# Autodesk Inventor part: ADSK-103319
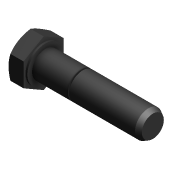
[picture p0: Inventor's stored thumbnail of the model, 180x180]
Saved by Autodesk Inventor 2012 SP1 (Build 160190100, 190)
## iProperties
Created: 2000-09
Part Number: ADSK-103319
Description: Hex Cap Screw
Document SubType Name: Modeling
Standard: ANSI B18.2.1 - 3/8 - 16 - 1 1/2
Designer: Administrator
Density: 1 g/cm^3
Material: Default
Control State: 0
Master: False
Checked Out: False
Shininess: 0.0
Density: 0.0
Volumn: 0.0
Area: 0.0
PropertySet Name: Model Information
Author: Administrator
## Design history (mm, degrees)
node "Base1"
body "Solid1"
